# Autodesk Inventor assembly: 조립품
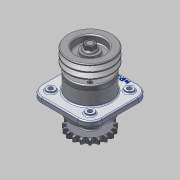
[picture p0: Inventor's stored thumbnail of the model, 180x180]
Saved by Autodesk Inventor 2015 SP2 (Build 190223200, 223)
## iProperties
Created: 2015-07
Part Number: 조립품
Document SubType Name: Assembly
Designer: AMC
Author: AMC
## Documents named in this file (12)
- C:\Users\AMC\Desktop\450735V1001\조립품.iam
- C:\Users\AMC\Desktop\450735V1001\2-커버.ipt
- C:\Users\AMC\Desktop\450735V1001\3-축.ipt
- C:\Users\AMC\Desktop\450735V1001\4-V벨트풀리.ipt
- C:\Users\AMC\Desktop\450735V1001\5-체인 스프로킷.ipt
- C:\Users\AMC\Desktop\450735V1001\6-베어링 6206.ipt
- C:\Users\AMC\Desktop\450735V1001\7-부시.ipt
- C:\Users\AMC\Desktop\450735V1001\8-오일실 30x42.ipt
- C:\Users\AMC\Desktop\450735V1001\9-M16-너트.ipt
- C:\Users\AMC\Desktop\450735V1001\10-M6.ipt
- C:\Users\AMC\Desktop\450735V1001\11-키 6x6.ipt
- C:\Users\AMC\Desktop\450735V1001\본체.ipt
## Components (22 placed, 10 different names)
1. 2-커버:1
2. 3-축:1
3. 4-V벨트풀리:1
4. 5-체인 스프로킷:1
5. 6-베어링 6206:1
6. 7-부시:1 — 플러쉬:4
7. 8-8-오일실 30x42:1
8. 9-M16 너트:1
9. 10-M6:1
10. 11-키 6x6:1
11. 2-커버:2
12. 6-베어링 6206:2
13. 8-8-오일실 30x42:2
14. 9-M16 너트:2
15. 10-M6:2
16. 10-M6:3
17. 10-M6:4
18. 10-M6:5
19. 10-M6:6
20. 10-M6:7
21. 10-M6:8
22. 11-키 6x6:2
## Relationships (1: Flush 1)
- 플러쉬:4 [Flush]: 7-부시:1
